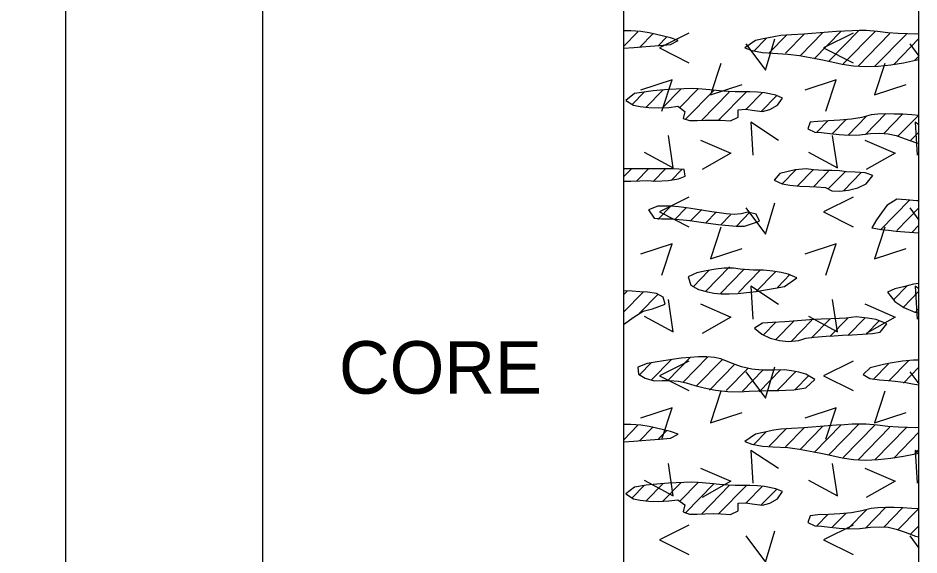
# Model space of a CAD drawing. Extents: x 0 to 0.833, y -0.323 to 0.608.
# Drawn here: x 0.719 to 0.8333, y -0.0873 to -0.0191 of the extents above; entities that cross this region are included whole.
import ezdxf

# ---------------------------------------------------------------- set-up
doc = ezdxf.new("R2010")
doc.units = 0

msp = doc.modelspace()

# ---------------------------------------------------------------- linework, layer by layer
for points in [[(0, -0.32328), (0.83333, -0.32328), (0.83333, 0.60833), (0, 0.60833)], [(0.79583, -0.02296), (0.79715, -0.02285), (0.79814, -0.02278), (0.79922, -0.0227), (0.80039, -0.02261), (0.80179, -0.02249), (0.80275, -0.02198), (0.80179, -0.02164), (0.80091, -0.02142), (0.80003, -0.0212), (0.79909, -0.02099), (0.79803, -0.02083), (0.79677, -0.02073), (0.79583, -0.02075)], [(0.82816, -0.02521), (0.82978, -0.02504), (0.83137, -0.02479), (0.8329, -0.02447), (0.83333, -0.02437), (0.83333, -0.02113), (0.83295, -0.02116), (0.83188, -0.02114), (0.83071, -0.02109), (0.82938, -0.02099), (0.82807, -0.02082), (0.82662, -0.0207), (0.82576, -0.02069), (0.82484, -0.02072), (0.82387, -0.02077), (0.82286, -0.02084), (0.82182, -0.02092), (0.82077, -0.021), (0.81973, -0.02109), (0.81872, -0.02116), (0.81715, -0.02126), (0.81579, -0.02135), (0.81491, -0.02148), (0.81357, -0.02176), (0.8126, -0.02197), (0.81121, -0.02289), (0.8121, -0.02325), (0.81345, -0.0235), (0.81479, -0.02359), (0.81668, -0.02369), (0.81818, -0.02389), (0.81905, -0.02404), (0.82, -0.02422), (0.82107, -0.02443), (0.82225, -0.02468), (0.82357, -0.02497), (0.82501, -0.0252), (0.82656, -0.02527)], [(0.79708, -0.03019), (0.79794, -0.03037), (0.79904, -0.03048), (0.80028, -0.03051), (0.80156, -0.03046), (0.80274, -0.0303), (0.80361, -0.03097), (0.80338, -0.03186), (0.80422, -0.03213), (0.80517, -0.03215), (0.80613, -0.0321), (0.8072, -0.03207), (0.80818, -0.0321), (0.80939, -0.03217), (0.81037, -0.0317), (0.81038, -0.03076), (0.8113, -0.03069), (0.81244, -0.03088), (0.81346, -0.03099), (0.81438, -0.03073), (0.81539, -0.03019), (0.81601, -0.02928), (0.81517, -0.0289), (0.81374, -0.02863), (0.81285, -0.02854), (0.81187, -0.02848), (0.81, -0.02848), (0.8091, -0.02846), (0.808, -0.02838), (0.80678, -0.02823), (0.8053, -0.0281), (0.80443, -0.02808), (0.80349, -0.0281), (0.80251, -0.02814), (0.80152, -0.0282), (0.80054, -0.02828), (0.79959, -0.02837), (0.7987, -0.02847), (0.79722, -0.02869), (0.79614, -0.02957)], [(0.83241, -0.03141), (0.83129, -0.03134), (0.83017, -0.03131), (0.8291, -0.0313), (0.82811, -0.03134), (0.82728, -0.03143), (0.82608, -0.03173), (0.82476, -0.03196), (0.8233, -0.03209), (0.82183, -0.03218), (0.82051, -0.03224), (0.81951, -0.03233), (0.81922, -0.0332), (0.82013, -0.03362), (0.82097, -0.03367), (0.822, -0.03377), (0.82318, -0.0339), (0.82448, -0.03399), (0.82584, -0.03396), (0.82719, -0.0338), (0.82836, -0.03373), (0.8294, -0.03381), (0.83043, -0.03404), (0.83156, -0.03444), (0.83291, -0.03493), (0.83333, -0.035), (0.83333, -0.03148)], [(0.79583, -0.03982), (0.79676, -0.03983), (0.79792, -0.03981), (0.79882, -0.03977), (0.79992, -0.03982), (0.80151, -0.03977), (0.80282, -0.03952), (0.80367, -0.0392), (0.80354, -0.03836), (0.80216, -0.03827), (0.79583, -0.03827)], [(0.81822, -0.04047), (0.81944, -0.04052), (0.82033, -0.04057), (0.82145, -0.04063), (0.82229, -0.04105), (0.82324, -0.04109), (0.82438, -0.04099), (0.82555, -0.0407), (0.82662, -0.04019), (0.82749, -0.0391), (0.82651, -0.03879), (0.82524, -0.03869), (0.82413, -0.03863), (0.82324, -0.03852), (0.82226, -0.0385), (0.82121, -0.03848), (0.81995, -0.03839), (0.81902, -0.03827), (0.81761, -0.03841), (0.81566, -0.03885), (0.81496, -0.03969), (0.81598, -0.04018), (0.81695, -0.04036)], [(0.83305, -0.04232), (0.83171, -0.04221), (0.83054, -0.04211), (0.82925, -0.04293), (0.82857, -0.04384), (0.82792, -0.04473), (0.82735, -0.04575), (0.82858, -0.04598), (0.82945, -0.04608), (0.83045, -0.04618), (0.83155, -0.04627), (0.83272, -0.04637), (0.83333, -0.04642), (0.83333, -0.04233)], [(0.80066, -0.04462), (0.80188, -0.04463), (0.80339, -0.04476), (0.80423, -0.04485), (0.8051, -0.04496), (0.806, -0.04508), (0.80692, -0.0452), (0.80784, -0.04532), (0.80875, -0.04543), (0.81014, -0.04557), (0.81119, -0.04556), (0.81222, -0.04522), (0.81308, -0.04493), (0.81267, -0.04403), (0.8116, -0.04378), (0.81075, -0.04398), (0.80989, -0.04406), (0.80885, -0.04398), (0.80799, -0.04387), (0.80703, -0.04373), (0.806, -0.04356), (0.80492, -0.0434), (0.80384, -0.04324), (0.8028, -0.04311), (0.80182, -0.04301), (0.8002, -0.04301), (0.79901, -0.04348), (0.79974, -0.04452)], [(0.81233, -0.05113), (0.81063, -0.05101), (0.80977, -0.05088), (0.8086, -0.05087), (0.80755, -0.05101), (0.80632, -0.05121), (0.80513, -0.05146), (0.80403, -0.05198), (0.80436, -0.05304), (0.80536, -0.0536), (0.80647, -0.0539), (0.8073, -0.05405), (0.80824, -0.05413), (0.80926, -0.05414), (0.81035, -0.05409), (0.81149, -0.05398), (0.81267, -0.05384), (0.81386, -0.05365), (0.81506, -0.05344), (0.81625, -0.05321), (0.81783, -0.05213), (0.81673, -0.05163), (0.81585, -0.05142), (0.8148, -0.05127), (0.81361, -0.05116)], [(0.83265, -0.05294), (0.83136, -0.05325), (0.83028, -0.05352), (0.82934, -0.05392), (0.83026, -0.05512), (0.83142, -0.05588), (0.83279, -0.05646), (0.83333, -0.05656), (0.83333, -0.05285)], [(0.79583, -0.05804), (0.79719, -0.05705), (0.79831, -0.05635), (0.79951, -0.05607), (0.80111, -0.05547), (0.80086, -0.05459), (0.80002, -0.05411), (0.79889, -0.05392), (0.79791, -0.05389), (0.79694, -0.05383), (0.79583, -0.05375)], [(0.82537, -0.05709), (0.82408, -0.05724), (0.82319, -0.0573), (0.82214, -0.05733), (0.82091, -0.05736), (0.81947, -0.05745), (0.81792, -0.05757), (0.81632, -0.05769), (0.81475, -0.05779), (0.81348, -0.05789), (0.81247, -0.05853), (0.81337, -0.05929), (0.81444, -0.05979), (0.81561, -0.06008), (0.81675, -0.06019), (0.81807, -0.06007), (0.81896, -0.0598), (0.82003, -0.05965), (0.82157, -0.05953), (0.82253, -0.05947), (0.82362, -0.05942), (0.82483, -0.05935), (0.82618, -0.05929), (0.82745, -0.05918), (0.82842, -0.059), (0.82927, -0.05795), (0.82791, -0.05743), (0.82679, -0.05723)], [(0.79885, -0.063), (0.79763, -0.06346), (0.79773, -0.06436), (0.79859, -0.06488), (0.7997, -0.06518), (0.80074, -0.06517), (0.80165, -0.06516), (0.80281, -0.06524), (0.80377, -0.06545), (0.80486, -0.0658), (0.80606, -0.06609), (0.80751, -0.06637), (0.80905, -0.06655), (0.81052, -0.06658), (0.81177, -0.06653), (0.81289, -0.06648), (0.81408, -0.06645), (0.81553, -0.06641), (0.81642, -0.06638), (0.81745, -0.06635), (0.81897, -0.06608), (0.82011, -0.06504), (0.81896, -0.06437), (0.8181, -0.06411), (0.81717, -0.06391), (0.81626, -0.0638), (0.81479, -0.06386), (0.81343, -0.06386), (0.8121, -0.06371), (0.8108, -0.06341), (0.80953, -0.06295), (0.8082, -0.0624), (0.80736, -0.06224), (0.8064, -0.06216), (0.80536, -0.06216), (0.80427, -0.06222), (0.80314, -0.06233), (0.80201, -0.06248), (0.8009, -0.06265), (0.79984, -0.06282)], [(0.83263, -0.06256), (0.83126, -0.06269), (0.82969, -0.06296), (0.82883, -0.06313), (0.82712, -0.06354), (0.82623, -0.06441), (0.82708, -0.0649), (0.82831, -0.06509), (0.82941, -0.06516), (0.83033, -0.06524), (0.83165, -0.06543), (0.83253, -0.06557), (0.83333, -0.06571), (0.83333, -0.06256)], [(0.79583, -0.07296), (0.79715, -0.07285), (0.79814, -0.07278), (0.79922, -0.0727), (0.80039, -0.07261), (0.80179, -0.07249), (0.80275, -0.07198), (0.80179, -0.07164), (0.80091, -0.07142), (0.80003, -0.0712), (0.79909, -0.07099), (0.79803, -0.07083), (0.79677, -0.07073), (0.79583, -0.07075)], [(0.82816, -0.07521), (0.82978, -0.07504), (0.83137, -0.07479), (0.8329, -0.07447), (0.83333, -0.07437), (0.83333, -0.07113), (0.83295, -0.07116), (0.83188, -0.07114), (0.83071, -0.07109), (0.82938, -0.07099), (0.82807, -0.07082), (0.82662, -0.0707), (0.82576, -0.07069), (0.82484, -0.07072), (0.82387, -0.07077), (0.82286, -0.07084), (0.82182, -0.07092), (0.82077, -0.071), (0.81973, -0.07109), (0.81872, -0.07116), (0.81715, -0.07126), (0.81579, -0.07135), (0.81491, -0.07148), (0.81357, -0.07176), (0.8126, -0.07197), (0.81121, -0.07289), (0.8121, -0.07325), (0.81345, -0.0735), (0.81479, -0.07359), (0.81668, -0.07369), (0.81818, -0.07389), (0.81905, -0.07404), (0.82, -0.07422), (0.82107, -0.07443), (0.82225, -0.07468), (0.82357, -0.07497), (0.82501, -0.0752), (0.82656, -0.07527)], [(0.79708, -0.08019), (0.79794, -0.08037), (0.79904, -0.08048), (0.80028, -0.08051), (0.80156, -0.08046), (0.80274, -0.0803), (0.80361, -0.08097), (0.80338, -0.08186), (0.80422, -0.08213), (0.80517, -0.08215), (0.80613, -0.0821), (0.8072, -0.08207), (0.80818, -0.0821), (0.80939, -0.08217), (0.81037, -0.0817), (0.81038, -0.08076), (0.8113, -0.08069), (0.81244, -0.08088), (0.81346, -0.08099), (0.81438, -0.08073), (0.81539, -0.08019), (0.81601, -0.07928), (0.81517, -0.0789), (0.81374, -0.07863), (0.81285, -0.07854), (0.81187, -0.07848), (0.81, -0.07848), (0.8091, -0.07846), (0.808, -0.07838), (0.80678, -0.07823), (0.8053, -0.0781), (0.80443, -0.07808), (0.80349, -0.0781), (0.80251, -0.07814), (0.80152, -0.0782), (0.80054, -0.07828), (0.79959, -0.07837), (0.7987, -0.07847), (0.79722, -0.07869), (0.79614, -0.07957)], [(0.83241, -0.08141), (0.83129, -0.08134), (0.83017, -0.08131), (0.8291, -0.0813), (0.82811, -0.08134), (0.82728, -0.08143), (0.82608, -0.08173), (0.82476, -0.08196), (0.8233, -0.08209), (0.82183, -0.08218), (0.82051, -0.08224), (0.81951, -0.08233), (0.81922, -0.0832), (0.82013, -0.08362), (0.82097, -0.08367), (0.822, -0.08377), (0.82318, -0.0839), (0.82448, -0.08399), (0.82584, -0.08396), (0.82719, -0.0838), (0.82836, -0.08373), (0.8294, -0.08381), (0.83043, -0.08404), (0.83156, -0.08444), (0.83291, -0.08493), (0.83333, -0.085), (0.83333, -0.08148)]]:
    msp.add_lwpolyline(points, close=True)
for points in [[(0.725, 0.55417), (0.725, -0.28575)], [(0.75, 0.55417), (0.75, -0.28575)], [(0.75, 0.55417), (0.75, -0.28575)], [(0.79583, 0.55417), (0.79583, -0.28575)], [(0.725, 0.54167), (0.725, -0.28575)], [(0.83333, -0.28575), (0.83333, 0.50165)], [(0.79765, -0.02085), (0.79583, -0.02272)], [(0.7996, -0.02106), (0.79786, -0.02284)], [(0.8013, -0.02154), (0.80027, -0.02259)], [(0.80412, -0.02104), (0.80038, -0.02291), (0.80412, -0.02479)], [(0.81392, -0.0217), (0.81235, -0.02331)], [(0.8143, -0.02352), (0.8165, -0.02127)], [(0.8164, -0.02359), (0.81879, -0.02114)], [(0.81829, -0.02387), (0.82114, -0.02095)], [(0.82004, -0.02429), (0.82346, -0.02078)], [(0.82496, -0.02104), (0.82121, -0.02291), (0.82496, -0.02479)], [(0.82569, -0.0207), (0.82184, -0.02465)], [(0.82775, -0.02081), (0.8237, -0.02495)], [(0.82964, -0.02108), (0.82557, -0.02526)], [(0.83173, -0.02115), (0.82774, -0.02524)], [(0.83333, -0.02173), (0.83012, -0.02502)], [(0.81134, -0.02238), (0.81384, -0.02575), (0.81503, -0.02175)], [(0.83217, -0.02238), (0.83333, -0.02394)], [(0.83281, -0.02448), (0.83333, -0.02394)], [(0.80818, -0.02487), (0.80687, -0.02887), (0.81087, -0.02755)], [(0.82901, -0.02487), (0.8277, -0.02887), (0.8317, -0.02755)], [(0.80069, -0.03095), (0.802, -0.02695), (0.798, -0.02826)], [(0.82152, -0.03095), (0.82284, -0.02695), (0.81884, -0.02826)], [(0.79844, -0.02851), (0.79691, -0.03008)], [(0.79871, -0.03045), (0.80085, -0.02825)], [(0.80083, -0.03049), (0.80311, -0.02815)], [(0.80534, -0.02807), (0.80299, -0.03049)], [(0.80367, -0.032), (0.80732, -0.02826)], [(0.80571, -0.03212), (0.80924, -0.02851)], [(0.81142, -0.02849), (0.80785, -0.03214)], [(0.81141, -0.03071), (0.81348, -0.02859)], [(0.81528, -0.02895), (0.81331, -0.03097)], [(0.82433, -0.03398), (0.82666, -0.03159)], [(0.82909, -0.0313), (0.82656, -0.0339)], [(0.82885, -0.03377), (0.83122, -0.03134)], [(0.83325, -0.03148), (0.83065, -0.03414)], [(0.81551, -0.03467), (0.81201, -0.03236), (0.81226, -0.03655)], [(0.82035, -0.03363), (0.82176, -0.03218)], [(0.82233, -0.03381), (0.82408, -0.03202)], [(0.83333, -0.03268), (0.83284, -0.03236), (0.83309, -0.03655)], [(0.79847, -0.03616), (0.80215, -0.03816), (0.80153, -0.03403)], [(0.8193, -0.03616), (0.82299, -0.03816), (0.82236, -0.03403)], [(0.83333, -0.0336), (0.83227, -0.03469)], [(0.80562, -0.03461), (0.80946, -0.03629), (0.80581, -0.03836)], [(0.82645, -0.03461), (0.83029, -0.03629), (0.82664, -0.03836)], [(0.79583, -0.0393), (0.79681, -0.0383)], [(0.79898, -0.03828), (0.79747, -0.03983)], [(0.80116, -0.03827), (0.79959, -0.03987)], [(0.80328, -0.03831), (0.80188, -0.03974)], [(0.8177, -0.03841), (0.81596, -0.04019)], [(0.81988, -0.03839), (0.81785, -0.04047)], [(0.82185, -0.03858), (0.81997, -0.04051)], [(0.824, -0.03859), (0.82178, -0.04087)], [(0.82601, -0.03875), (0.82378, -0.04103)], [(0.80412, -0.04187), (0.80038, -0.04374), (0.80412, -0.04562)], [(0.82496, -0.04187), (0.82121, -0.04374), (0.82496, -0.04562)], [(0.83217, -0.04219), (0.82844, -0.04601)], [(0.80188, -0.04297), (0.8002, -0.04469)], [(0.8038, -0.04321), (0.80237, -0.04467)], [(0.80575, -0.04343), (0.80429, -0.04492)], [(0.81134, -0.04321), (0.81384, -0.04658), (0.81503, -0.04258)], [(0.83333, -0.04321), (0.83052, -0.04609)], [(0.83217, -0.04321), (0.83333, -0.04477)], [(0.80758, -0.04376), (0.80627, -0.04511)], [(0.80941, -0.0441), (0.80816, -0.04538)], [(0.81188, -0.04378), (0.81016, -0.04554)], [(0.80818, -0.0457), (0.80687, -0.0497), (0.81087, -0.04839)], [(0.82901, -0.0457), (0.8277, -0.0497), (0.8317, -0.04839)], [(0.83333, -0.04543), (0.83245, -0.04633)], [(0.80069, -0.05178), (0.802, -0.04778), (0.798, -0.04909)], [(0.82152, -0.05178), (0.82284, -0.04778), (0.81884, -0.04909)], [(0.80465, -0.05325), (0.80667, -0.05117)], [(0.80626, -0.05381), (0.80928, -0.05071)], [(0.80809, -0.05414), (0.81111, -0.05105)], [(0.81041, -0.05398), (0.81318, -0.05115)], [(0.81264, -0.0539), (0.81518, -0.0513)], [(0.81536, -0.05333), (0.81699, -0.05167)], [(0.81551, -0.05551), (0.81201, -0.05319), (0.81226, -0.05738)], [(0.8301, -0.05491), (0.83184, -0.05312)], [(0.83333, -0.05352), (0.83284, -0.05319), (0.83309, -0.05738)], [(0.7963, -0.05379), (0.79583, -0.05427)], [(0.79834, -0.05392), (0.79583, -0.05649)], [(0.79786, -0.05662), (0.80023, -0.05419)], [(0.79847, -0.05699), (0.80215, -0.05899), (0.80153, -0.05486)], [(0.8193, -0.05699), (0.82299, -0.05899), (0.82236, -0.05486)], [(0.83131, -0.05588), (0.83333, -0.05381)], [(0.80562, -0.05544), (0.80946, -0.05713), (0.80581, -0.05919)], [(0.82645, -0.05544), (0.83029, -0.05713), (0.82664, -0.05919)], [(0.83285, -0.05651), (0.83333, -0.05602)], [(0.81519, -0.05772), (0.81354, -0.05942)], [(0.81514, -0.05998), (0.81748, -0.05759)], [(0.81709, -0.0602), (0.81974, -0.05749)], [(0.8197, -0.05975), (0.82203, -0.05735)], [(0.82202, -0.05958), (0.8243, -0.05725)], [(0.82431, -0.05945), (0.82644, -0.05726)], [(0.82663, -0.05928), (0.82834, -0.05753)], [(0.79938, -0.06287), (0.79786, -0.06442)], [(0.79933, -0.06513), (0.80195, -0.06244)], [(0.80412, -0.0627), (0.80038, -0.06458), (0.80412, -0.06645)], [(0.80142, -0.0652), (0.8043, -0.06225)], [(0.80653, -0.06217), (0.8034, -0.06539)], [(0.80506, -0.06589), (0.8084, -0.06247)], [(0.82496, -0.0627), (0.82121, -0.06458), (0.82496, -0.06645)], [(0.83203, -0.06261), (0.82949, -0.06521)], [(0.80997, -0.06307), (0.80675, -0.06638)], [(0.81164, -0.06358), (0.80884, -0.06644)], [(0.81353, -0.06386), (0.81094, -0.06651)], [(0.81134, -0.06404), (0.81384, -0.06742), (0.81503, -0.06342)], [(0.81303, -0.06658), (0.81579, -0.06375)], [(0.81534, -0.06642), (0.81768, -0.06402)], [(0.82751, -0.06502), (0.82945, -0.06303)], [(0.83138, -0.06548), (0.83333, -0.06348)], [(0.8176, -0.06632), (0.81934, -0.06453)], [(0.83217, -0.06404), (0.83333, -0.0656)], [(0.83333, -0.0657), (0.83333, -0.06569)], [(0.80818, -0.06653), (0.80687, -0.07053), (0.81087, -0.06922)], [(0.82901, -0.06653), (0.8277, -0.07053), (0.8317, -0.06922)], [(0.80069, -0.07261), (0.802, -0.06861), (0.798, -0.06993)], [(0.82152, -0.07261), (0.82284, -0.06861), (0.81884, -0.06993)], [(0.79765, -0.07085), (0.79583, -0.07272)], [(0.82004, -0.07429), (0.82346, -0.07078)], [(0.82569, -0.0707), (0.82184, -0.07465)], [(0.82775, -0.07081), (0.8237, -0.07495)], [(0.7996, -0.07106), (0.79786, -0.07284)], [(0.8013, -0.07154), (0.80027, -0.07259)], [(0.81392, -0.0717), (0.81235, -0.07331)], [(0.8143, -0.07352), (0.8165, -0.07127)], [(0.8164, -0.07359), (0.81879, -0.07114)], [(0.81829, -0.07387), (0.82114, -0.07095)], [(0.82964, -0.07108), (0.82557, -0.07526)], [(0.83173, -0.07115), (0.82774, -0.07524)], [(0.83333, -0.07173), (0.83012, -0.07502)], [(0.81551, -0.07634), (0.81201, -0.07403), (0.81226, -0.07821)], [(0.83281, -0.07448), (0.83333, -0.07394)], [(0.83333, -0.07435), (0.83284, -0.07403), (0.83309, -0.07821)], [(0.79847, -0.07782), (0.80215, -0.07982), (0.80153, -0.0757)], [(0.80562, -0.07628), (0.80946, -0.07796), (0.80581, -0.08002)], [(0.8193, -0.07782), (0.82299, -0.07982), (0.82236, -0.0757)], [(0.82645, -0.07628), (0.83029, -0.07796), (0.82664, -0.08002)], [(0.79844, -0.07851), (0.79691, -0.08008)], [(0.79871, -0.08045), (0.80085, -0.07825)], [(0.80083, -0.08049), (0.80311, -0.07815)], [(0.80534, -0.07807), (0.80299, -0.08049)], [(0.80367, -0.082), (0.80732, -0.07826)], [(0.80571, -0.08212), (0.80924, -0.07851)], [(0.81142, -0.07849), (0.80785, -0.08214)], [(0.81141, -0.08071), (0.81348, -0.07859)], [(0.81528, -0.07895), (0.81331, -0.08097)], [(0.82035, -0.08363), (0.82176, -0.08218)], [(0.82233, -0.08381), (0.82408, -0.08202)], [(0.82433, -0.08398), (0.82666, -0.08159)], [(0.82909, -0.0813), (0.82656, -0.0839)], [(0.82885, -0.08377), (0.83122, -0.08134)], [(0.83325, -0.08148), (0.83065, -0.08414)], [(0.80412, -0.08353), (0.80038, -0.08541), (0.80412, -0.08728)], [(0.81134, -0.08488), (0.81384, -0.08825), (0.81503, -0.08425)], [(0.82496, -0.08353), (0.82121, -0.08541), (0.82496, -0.08728)], [(0.83333, -0.0836), (0.83227, -0.08469)], [(0.83217, -0.08488), (0.83333, -0.08644)]]:
    msp.add_lwpolyline(points)

# ---------------------------------------------------------------- texts
msp.add_text('CORE', height=0.006667).set_placement((0.75971, -0.06683))

doc.saveas('drawing.dxf')
